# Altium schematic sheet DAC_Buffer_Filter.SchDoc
size A4; Organization: HTL Hollabrunn; Address1: Abteilung Elektronik; Address2: Anton Ehrenfried-Straße 10; Address3: 2020 Hollabrunn; SPICEModelCacheDRLOHMHD: <root> / <DocumentId>DRLOHMHD</DocumentId> / <CacheFrame Number="0"> / <Model Name="cap" Kind="MDL"> / <Text>*Default semiconductor capacitor / .MODEL CAP C()</Text> / </Model> / </CacheFrame> / </root>
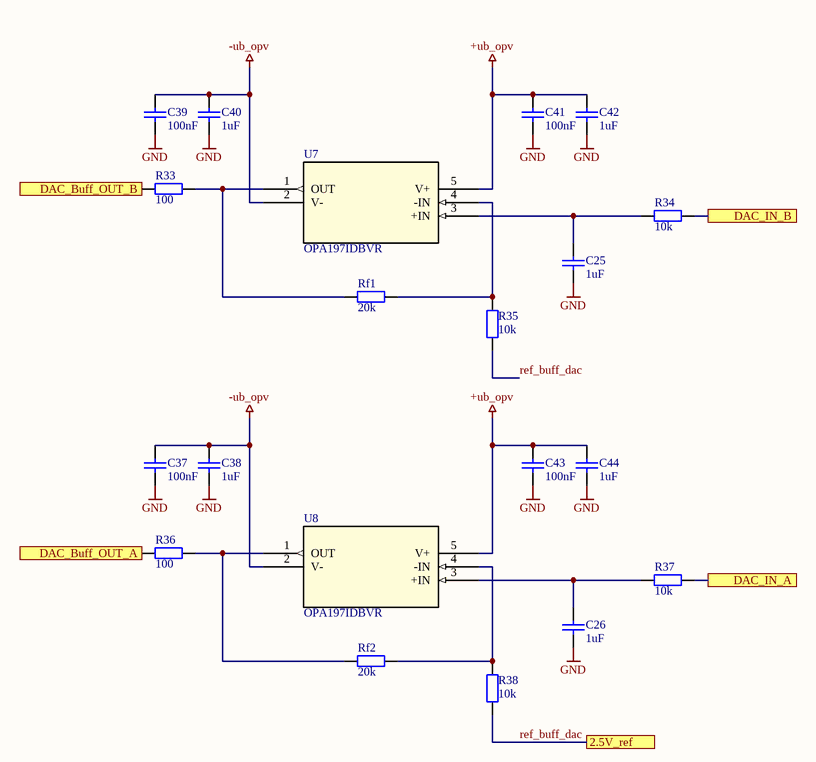
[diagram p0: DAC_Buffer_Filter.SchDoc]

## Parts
C25  1uF  [C1206-KUE]
C26  1uF  [C1206-KUE]
C37  100nF  [C1206-KUE]
C38  1uF  [C1206-KUE]
C39  100nF  [C1206-KUE]
C40  1uF  [C1206-KUE]
C41  100nF  [C1206-KUE]
C42  1uF  [C1206-KUE]
C43  100nF  [C1206-KUE]
C44  1uF  [C1206-KUE]
R33  100  [C1206-KUE]
R34  10k  [C1206-KUE]
R35  10k  [C1206-KUE]
R36  100  [C1206-KUE]
R37  10k  [C1206-KUE]
R38  10k  [C1206-KUE]
Rf1  20k  [C1206-KUE]
Rf2  20k  [C1206-KUE]
U7  OPA197IDBVR  [DBV5_TEX]
U8  OPA197IDBVR  [DBV5_TEX]

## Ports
2.5V_ref, DAC_Buff_OUT_A, DAC_Buff_OUT_B, DAC_IN_A, DAC_IN_B

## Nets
+ub_opv: C41.2 C42.2 C43.2 C44.2 U7.5(V+) U8.5(V+)
-ub_opv: C37.2 C38.2 C39.2 C40.2 U7.2(V-) U8.2(V-)
GND: C25.1 C26.1 C37.1 C38.1 C39.1 C40.1 C41.1 C42.1 C43.1 C44.1
DAC_Buff_OUT_A: R36.2 ; port DAC_Buff_OUT_A
DAC_Buff_OUT_B: R33.2 ; port DAC_Buff_OUT_B
DAC_IN_A: R37.1 ; port DAC_IN_A
DAC_IN_B: R34.1 ; port DAC_IN_B
ref_buff_dac: R35.1 R38.1 ; port 2.5V_ref
NetC25_2: C25.2 R34.2 U7.3(+IN)
NetC26_2: C26.2 R37.2 U8.3(+IN)
NetR33_1: R33.1 Rf1.2 U7.1(OUT)
NetR35_2: R35.2 Rf1.1 U7.4(-IN)
NetR36_1: R36.1 Rf2.2 U8.1(OUT)
NetR38_2: R38.2 Rf2.1 U8.4(-IN)

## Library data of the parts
C25 C26 C37-C44 = Capacitor: Manufacturer: Kemet; Bezeichnung: Kerko +-10% 63V
R33-R38 Rf1 Rf2 = ResistorSMD: Resistor SMD; Manufacturer: AVX; Bezeichnung: SMD Wid. 1/8W 2%
U7 U8 = OPA197IDBVR: Single, 36-V, precision, rail-to-rail input output, low offset voltage op amp 5-SOT-23 -40 to 125; Manufacturer_Name: Texas Instruments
